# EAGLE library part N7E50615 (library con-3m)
CONNECTOR PCMCIA-CompactFlash
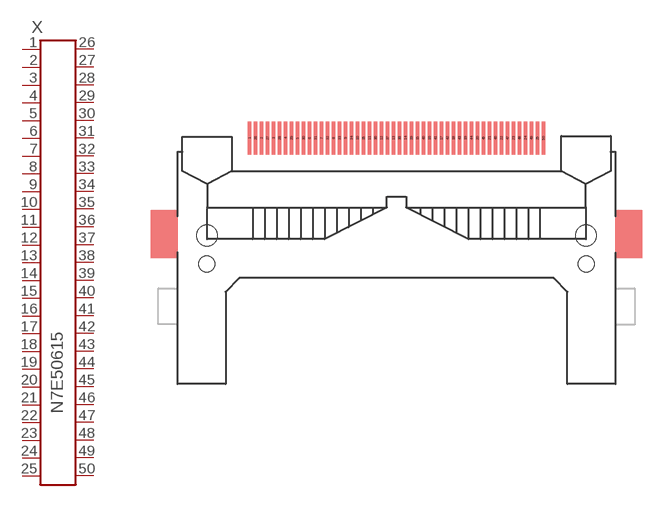
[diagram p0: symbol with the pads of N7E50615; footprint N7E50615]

Designator prefix X

## N7E50615  [N7E50615]
1  1  pas
2  2  pas
3  3  pas
4  4  pas
5  5  pas
6  6  pas
7  7  pas
8  8  pas
9  9  pas
10  10  pas
11  11  pas
12  12  pas
13  13  pas
14  14  pas
15  15  pas
16  16  pas
17  17  pas
18  18  pas
19  19  pas
20  20  pas
21  21  pas
22  22  pas
23  23  pas
24  24  pas
25  25  pas
26  26  pas
27  27  pas
28  28  pas
29  29  pas
30  30  pas
31  31  pas
32  32  pas
33  33  pas
34  34  pas
35  35  pas
36  36  pas
37  37  pas
38  38  pas
39  39  pas
40  40  pas
41  41  pas
42  42  pas
43  43  pas
44  44  pas
45  45  pas
46  46  pas
47  47  pas
48  48  pas
49  49  pas
50  50  pas

## Footprint N7E50615 (pad centres in mm)
CONNECTOR PCMCIA-CompactFlash
smd 0.4 x 3.5: 1 -15.557,10.335; 2 -14.287,10.335; 3 -13.018,10.335; 4 -11.748,10.335; 5 -10.477,10.335; 6 -9.207,10.335; 7 -7.938,10.335; 8 -6.668,10.335; 9 -5.397,10.335; 10 -4.128,10.335; 11 -2.857,10.335; 12 -1.587,10.335; 13 -0.318,10.335; 14 0.953,10.335; 15 2.223,10.335; 16 3.493,10.335; 17 4.763,10.335; 18 6.032,10.335; 19 7.303,10.335; 20 8.572,10.335; 21 9.842,10.335; 22 11.113,10.335; 23 12.383,10.335; 24 13.652,10.335; 25 14.922,10.335; 26 -14.922,10.335; 27 -13.652,10.335; 28 -12.383,10.335; 29 -11.113,10.335; 30 -9.842,10.335; 31 -8.572,10.335; 32 -7.303,10.335; 33 -6.032,10.335; 34 -4.763,10.335; 35 -3.493,10.335; 36 -2.223,10.335; 37 -0.953,10.335; 38 0.318,10.335; 39 1.587,10.335; 40 2.857,10.335; 41 4.128,10.335; 42 5.397,10.335; 43 6.668,10.335; 44 7.938,10.335; 45 9.207,10.335; 46 10.477,10.335; 47 11.748,10.335; 48 13.018,10.335; 49 14.287,10.335; 50 15.557,10.335
hole 1.7 at -20.08,-3
hole 1.7 at 20.08,-3
hole 2.2 at -20.08,0
hole 2.2 at 20.08,0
